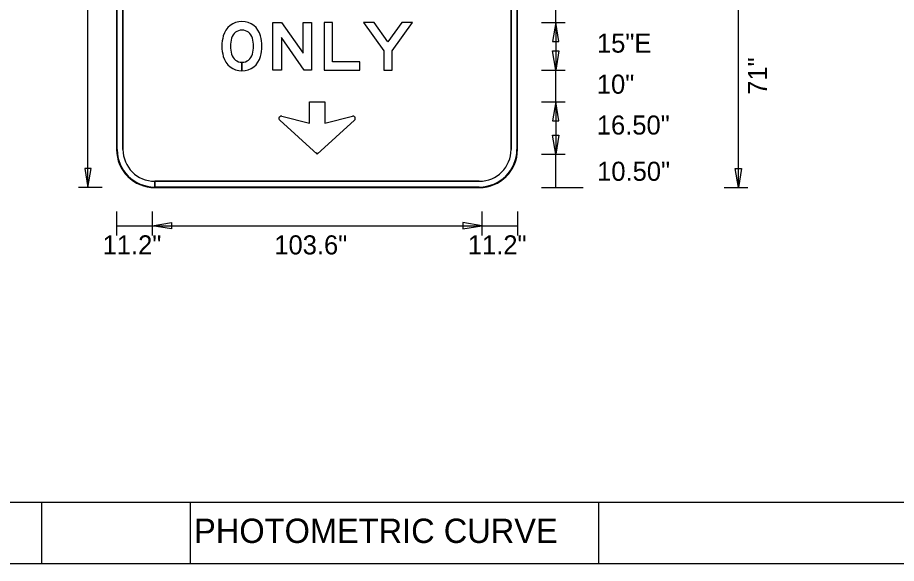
# Model space of a CAD drawing. Extents: x 119523 to 121850, y -23542 to -19972.
# Drawn here: x 121297.8 to 121574, y -23086 to -22914.3 of the extents above; entities that cross this region are included whole.
import ezdxf

# ---------------------------------------------------------------- set-up
doc = ezdxf.new("R2010")
doc.units = 0
for name, color, linetype in [('GSBWFill', 7, 'Continuous'), ('GSColorFill', 7, 'Continuous'), ('GSDims', 7, 'Continuous'), ('GSOutline', 7, 'Continuous'), ('SheetLinesMisc2_dp', 7, 'Continuous'), ('TextMinor', 7, 'Continuous')]:
    doc.layers.add(name, color=color, linetype=linetype)

msp = doc.modelspace()

# ---------------------------------------------------------------- linework, layer by layer
at = {"layer": 'GSBWFill'}
for p, q in [((121328.9, -22829.83), (121328.9, -22955.83)), ((121330.9, -22955.83), (121330.9, -22829.83)), ((121452.9, -22829.83), (121452.9, -22955.83)), ((121454.9, -22955.83), (121454.9, -22829.83)), ((121368.3, -22931.09), (121368.3, -22928.39)), ((121368.3, -22928.39), (121368.3, -22931.09)), ((121340.9, -22967.83), (121340.9, -22965.83)), ((121442.9, -22965.83), (121340.92, -22965.83)), ((121340.92, -22965.83), (121340.92, -22967.83)), ((121340.92, -22967.83), (121442.9, -22967.83))]:
    msp.add_line(p, q, dxfattribs=at)
for points in [[(121390.2, -22915.83), (121390.2, -22930.83), (121387.88, -22930.83), (121380.75, -22920.56), (121380.75, -22930.83), (121378.05, -22930.83), (121378.05, -22915.83), (121380.76, -22915.83), (121387.5, -22925.55), (121387.5, -22915.83)], [(121405.35, -22930.83), (121405.35, -22928.21), (121396.8, -22928.21), (121396.8, -22915.83), (121394.1, -22915.83), (121394.1, -22930.83)], [(121415.55, -22924.76), (121421.85, -22915.83), (121418.55, -22915.83), (121414.2, -22921.99), (121409.86, -22915.83), (121406.55, -22915.83), (121412.85, -22924.76), (121412.85, -22930.83), (121415.55, -22930.83)]]:
    msp.add_lwpolyline(points, close=True, dxfattribs=at)
for points in [[(121380.85, -22945.34), (121389.49, -22947.56), (121389.49, -22940.83), (121394.36, -22940.83), (121394.36, -22947.56), (121403, -22945.34)], [(121403.69, -22946.6), (121391.93, -22957.3), (121380.17, -22946.6)]]:
    msp.add_lwpolyline(points, dxfattribs=at)
for centre, radius, start, end in [((121368.3, -22921.65), 6.08, 14.9618, 165.0382), ((121368.3, -22921.65), 3.38, 14.9618, 165.0382), ((121374.6, -22923.33), 12.6, 165.0382, 194.9618), ((121374.6, -22923.33), 9.9, 165.0382, 194.9618), ((121362, -22923.33), 9.9, 345.0382, 14.9618), ((121362, -22923.33), 12.6, 345.0382, 14.9618), ((121368.3, -22925.01), 6.08, 194.9618, 270), ((121368.3, -22925.01), 3.38, 194.9618, 270), ((121368.3, -22925.01), 3.38, 270.0127, 345.0382), ((121368.3, -22925.01), 6.08, 270.0071, 345.0382), ((121380.67, -22946.06), 0.738, 75.5925, 227.6952), ((121403.19, -22946.06), 0.738, 312.3048, 104.4075), ((121340.9, -22955.83), 12, 180, 270), ((121340.9, -22955.83), 10, 180, 270), ((121442.9, -22955.83), 12, 270, 0), ((121442.9, -22955.83), 10, 270, 0)]:
    msp.add_arc(centre, radius, start, end, dxfattribs=at)
at = {"layer": 'GSColorFill'}
for p, q in [((121328.9, -22829.83), (121328.9, -22955.83)), ((121328.9, -22829.83), (121328.9, -22955.83)), ((121328.9, -22829.83), (121328.9, -22955.83)), ((121329.1, -22955.83), (121329.1, -22829.83)), ((121330.9, -22955.83), (121330.9, -22829.83)), ((121452.9, -22829.83), (121452.9, -22955.83)), ((121454.7, -22829.83), (121454.7, -22955.83)), ((121454.9, -22955.83), (121454.9, -22829.83)), ((121454.9, -22955.83), (121454.9, -22829.83)), ((121454.9, -22955.83), (121454.9, -22829.83)), ((121368.3, -22931.09), (121368.3, -22928.39)), ((121368.3, -22928.39), (121368.3, -22931.09)), ((121340.9, -22967.83), (121340.9, -22965.83)), ((121442.9, -22965.83), (121340.92, -22965.83)), ((121340.92, -22965.83), (121340.92, -22967.83)), ((121340.9, -22967.83), (121340.9, -22967.63)), ((121442.9, -22967.63), (121340.9, -22967.63)), ((121340.9, -22967.63), (121340.9, -22967.83)), ((121340.9, -22967.83), (121442.9, -22967.83)), ((121340.9, -22967.83), (121442.9, -22967.83)), ((121340.92, -22967.83), (121442.9, -22967.83))]:
    msp.add_line(p, q, dxfattribs=at)
for points in [[(121390.2, -22915.83), (121390.2, -22930.83), (121387.88, -22930.83), (121380.75, -22920.56), (121380.75, -22930.83), (121378.05, -22930.83), (121378.05, -22915.83), (121380.76, -22915.83), (121387.5, -22925.55), (121387.5, -22915.83)], [(121405.35, -22930.83), (121405.35, -22928.21), (121396.8, -22928.21), (121396.8, -22915.83), (121394.1, -22915.83), (121394.1, -22930.83)], [(121415.55, -22924.76), (121421.85, -22915.83), (121418.55, -22915.83), (121414.2, -22921.99), (121409.86, -22915.83), (121406.55, -22915.83), (121412.85, -22924.76), (121412.85, -22930.83), (121415.55, -22930.83)]]:
    msp.add_lwpolyline(points, close=True, dxfattribs=at)
for points in [[(121380.85, -22945.34), (121389.49, -22947.56), (121389.49, -22940.83), (121394.36, -22940.83), (121394.36, -22947.56), (121403, -22945.34)], [(121403.69, -22946.6), (121391.93, -22957.3), (121380.17, -22946.6)]]:
    msp.add_lwpolyline(points, dxfattribs=at)
for centre, radius, start, end in [((121368.3, -22921.65), 6.08, 14.9618, 165.0382), ((121368.3, -22921.65), 3.38, 14.9618, 165.0382), ((121374.6, -22923.33), 12.6, 165.0382, 194.9618), ((121374.6, -22923.33), 9.9, 165.0382, 194.9618), ((121362, -22923.33), 9.9, 345.0382, 14.9618), ((121362, -22923.33), 12.6, 345.0382, 14.9618), ((121368.3, -22925.01), 6.08, 194.9618, 270), ((121368.3, -22925.01), 3.38, 194.9618, 270), ((121368.3, -22925.01), 3.38, 270.0127, 345.0382), ((121368.3, -22925.01), 6.08, 270.0071, 345.0382), ((121380.67, -22946.06), 0.738, 75.5925, 227.6952), ((121403.19, -22946.06), 0.738, 312.3048, 104.4075), ((121340.9, -22955.83), 12, 180, 270), ((121340.9, -22955.83), 12, 180, 270), ((121340.9, -22955.83), 12, 180, 270), ((121340.9, -22955.83), 11.8, 180, 270), ((121340.9, -22955.83), 10, 180, 270), ((121442.9, -22955.83), 12, 270, 0), ((121442.9, -22955.83), 12, 270, 0), ((121442.9, -22955.83), 10, 270, 0), ((121442.9, -22955.83), 12, 270, 0), ((121442.9, -22955.83), 11.8, 270, 0)]:
    msp.add_arc(centre, radius, start, end, dxfattribs=at)
at = {"layer": 'GSDims'}
for p, q in [((121319.9, -22967.83), (121319.9, -22817.83)), ((121524.31, -22967.83), (121524.31, -22896.83)), ((121466.9, -22915.83), (121466.9, -22905.83)), ((121462.4, -22915.83), (121469.9, -22915.83)), ((121462.4, -22915.83), (121469.9, -22915.83)), ((121466.9, -22915.83), (121466.9, -22930.83)), ((121462.4, -22930.83), (121469.9, -22930.83)), ((121462.4, -22930.83), (121469.9, -22930.83)), ((121466.9, -22940.83), (121466.9, -22930.83)), ((121462.4, -22940.83), (121469.9, -22940.83)), ((121462.4, -22940.83), (121469.9, -22940.83)), ((121466.9, -22940.83), (121466.9, -22957.3)), ((121391.78, -22956.83), (121391.97, -22956.83)), ((121462.4, -22957.3), (121469.9, -22957.3)), ((121462.4, -22957.3), (121469.9, -22957.3)), ((121466.9, -22967.83), (121466.9, -22957.3)), ((121324.4, -22967.83), (121316.9, -22967.83)), ((121324.4, -22967.83), (121324.4, -22967.83)), ((121462.4, -22967.83), (121469.9, -22967.83)), ((121462.4, -22967.83), (121475.54, -22967.83)), ((121519.81, -22967.83), (121527.31, -22967.83)), ((121328.9, -22975.33), (121328.9, -22982.83)), ((121328.9, -22975.33), (121328.9, -22982.83)), ((121340.12, -22975.33), (121340.12, -22982.83)), ((121340.12, -22975.33), (121340.12, -22982.83)), ((121443.68, -22975.33), (121443.68, -22982.83)), ((121443.68, -22975.33), (121443.68, -22982.83)), ((121454.9, -22975.33), (121454.9, -22982.83)), ((121454.9, -22975.33), (121454.9, -22982.83)), ((121328.9, -22979.83), (121340.12, -22979.83)), ((121340.12, -22979.83), (121443.68, -22979.83)), ((121443.68, -22979.83), (121454.9, -22979.83))]:
    msp.add_line(p, q, dxfattribs=at)
for points in [[(121466.9, -22915.83), (121465.9, -22921.83), (121467.9, -22921.83)], [(121466.9, -22930.83), (121465.9, -22924.83), (121467.9, -22924.83)], [(121466.9, -22940.83), (121465.9, -22946.83), (121467.9, -22946.83)], [(121466.9, -22957.3), (121465.9, -22951.3), (121467.9, -22951.3)], [(121319.9, -22967.83), (121320.9, -22961.83), (121318.9, -22961.83)], [(121524.31, -22967.83), (121523.31, -22961.83), (121525.31, -22961.83)], [(121340.12, -22979.83), (121346.12, -22978.83), (121346.12, -22980.83)], [(121443.68, -22979.83), (121437.68, -22978.83), (121437.68, -22980.83)]]:
    msp.add_lwpolyline(points, close=True, dxfattribs=at)
at = {"layer": 'GSOutline'}
for p, q in [((121328.9, -22829.83), (121328.9, -22955.83)), ((121330.9, -22829.83), (121330.9, -22955.83)), ((121452.9, -22955.83), (121452.9, -22829.83)), ((121454.9, -22955.83), (121454.9, -22829.83)), ((121340.9, -22965.83), (121442.9, -22965.83)), ((121340.9, -22967.83), (121442.9, -22967.83))]:
    msp.add_line(p, q, dxfattribs=at)
for points in [[(121390.2, -22915.83), (121390.2, -22930.83), (121387.88, -22930.83), (121380.75, -22920.56), (121380.75, -22930.83), (121378.05, -22930.83), (121378.05, -22915.83), (121380.76, -22915.83), (121387.5, -22925.55), (121387.5, -22915.83)], [(121405.35, -22930.83), (121405.35, -22928.21), (121396.8, -22928.21), (121396.8, -22915.83), (121394.1, -22915.83), (121394.1, -22930.83)], [(121415.55, -22924.76), (121421.85, -22915.83), (121418.55, -22915.83), (121414.2, -22921.99), (121409.86, -22915.83), (121406.55, -22915.83), (121412.85, -22924.76), (121412.85, -22930.83), (121415.55, -22930.83)]]:
    msp.add_lwpolyline(points, close=True, dxfattribs=at)
for points in [[(121380.85, -22945.34), (121389.49, -22947.56), (121389.49, -22940.83), (121394.36, -22940.83), (121394.36, -22947.56), (121403, -22945.34)], [(121403.69, -22946.6), (121391.93, -22957.3), (121380.17, -22946.6)]]:
    msp.add_lwpolyline(points, dxfattribs=at)
for centre, radius, start, end in [((121368.3, -22921.65), 6.08, 14.9618, 165.0382), ((121368.3, -22921.65), 3.38, 14.9618, 165.0382), ((121374.6, -22923.33), 12.6, 165.0382, 194.9618), ((121374.6, -22923.33), 9.9, 165.0382, 194.9618), ((121362, -22923.33), 9.9, 345.0382, 14.9618), ((121362, -22923.33), 12.6, 345.0382, 14.9618), ((121368.3, -22925.01), 6.08, 194.9618, 345.0382), ((121368.3, -22925.01), 3.38, 194.9618, 345.0382), ((121380.67, -22946.06), 0.738, 75.5925, 227.6952), ((121403.19, -22946.06), 0.738, 312.3048, 104.4075), ((121340.9, -22955.83), 12, 180, 270), ((121340.9, -22955.83), 10, 180, 270), ((121442.9, -22955.83), 12, 270, 0), ((121442.9, -22955.83), 10, 270, 0)]:
    msp.add_arc(centre, radius, start, end, dxfattribs=at)
at = {"layer": 'SheetLinesMisc2_dp'}
for p, q in [((121023.51, -23066.81), (121760.29, -23066.81)), ((121305.35, -23066.81), (121305.35, -23086.04)), ((121352.05, -23066.81), (121352.05, -23086.04)), ((121480.32, -23066.81), (121480.32, -23086.04)), ((121023.51, -23086.04), (121760.29, -23086.04))]:
    msp.add_line(p, q, dxfattribs=at)

# ---------------------------------------------------------------- texts
at = {"layer": 'GSDims'}
for s, p in [('15"E', (121479.87, -22925.36)), ('10"', (121479.84, -22938.28)), ('16.50"', (121479.83, -22951.13)), ('10.50"', (121479.93, -22965.68)), ('11.2"', (121324.51, -22988.83)), ('103.6"', (121378.47, -22988.83)), ('11.2"', (121439.29, -22988.83))]:
    msp.add_text(s, height=6, dxfattribs=at).set_placement(p)
msp.add_text('71"', height=6, rotation=90, dxfattribs=at).set_placement((121533.31, -22938.62))
at = {"layer": 'TextMinor'}
msp.add_text('PHOTOMETRIC CURVE', height=7.6529, dxfattribs=at).set_placement((121353.26, -23079.6))

doc.saveas('drawing.dxf')
